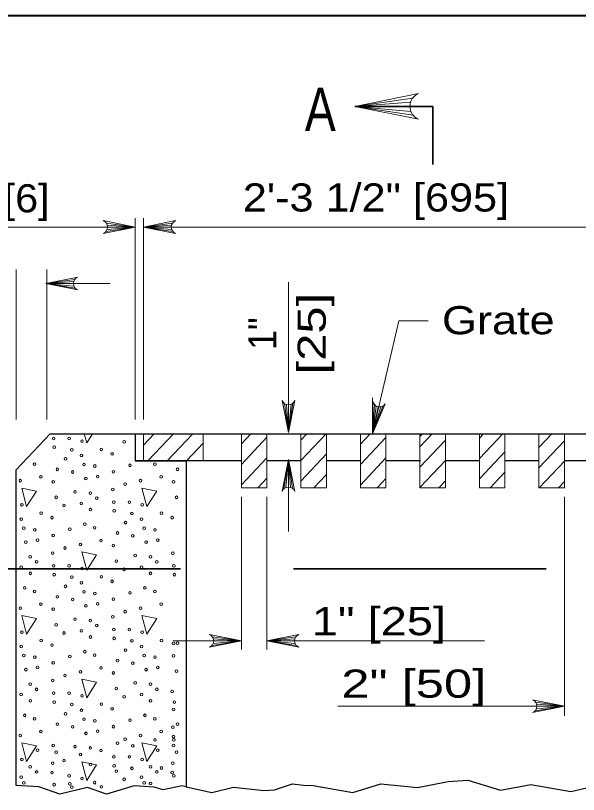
# Model space of a CAD drawing. Extents: x -410.5 to -376.5, y 1617.6 to 1661.6.
# Drawn here: x -394.78 to -391.656, y 1634.741 to 1639.062 of the extents above; entities that cross this region are included whole.
import ezdxf
from ezdxf.enums import TextEntityAlignment as Align

# ---------------------------------------------------------------- set-up
doc = ezdxf.new("R2010")
doc.units = 0
doc.header["$LTSCALE"] = 0.062
doc.layers.add('1', color=7, linetype='Continuous', lineweight=13)

msp = doc.modelspace()

# ---------------------------------------------------------------- linework, layer by layer
at = {"layer": '1', "lineweight": 25}
for p, q in [((-408.45475, 1639.06183), (-376.95475, 1639.06183)), ((-394.1165, 1636.74175), (-390.8125, 1636.74175)), ((-393.52675, 1636.59183), (-394.1165, 1636.59183)), ((-393.83325, 1636.59183), (-393.83325, 1634.78325)), ((-393.19667, 1636.59183), (-393.38483, 1636.59183)), ((-392.86658, 1636.59183), (-393.0545, 1636.59183)), ((-392.532, 1636.59183), (-392.72408, 1636.59183)), ((-392.20633, 1636.59183), (-392.39367, 1636.59183)), ((-391.87483, 1636.59183), (-392.06325, 1636.59183)), ((-391.54408, 1636.59183), (-391.73283, 1636.59183))]:
    msp.add_line(p, q, dxfattribs=at)
at = {"layer": '1'}
for p, q in [((-392.57667, 1638.603), (-392.89717, 1638.55817)), ((-392.5875, 1638.58083), (-392.89717, 1638.55817)), ((-392.59083, 1638.55817), (-392.89717, 1638.55817)), ((-392.58517, 1638.52933), (-392.89717, 1638.55817)), ((-392.57283, 1638.50858), (-392.89717, 1638.55817)), ((-394.1165, 1636.82042), (-394.1165, 1637.93875)), ((-394.06925, 1636.82042), (-394.06925, 1637.93875)), ((-395.37925, 1637.88875), (-394.1165, 1637.88875)), ((-394.27858, 1637.864), (-394.1165, 1637.88875)), ((-394.27675, 1637.91117), (-394.1165, 1637.88875)), ((-394.2725, 1637.87442), (-394.1165, 1637.88875)), ((-394.27125, 1637.90008), (-394.1165, 1637.88875)), ((-394.26967, 1637.88875), (-394.1165, 1637.88875)), ((-393.909, 1637.91117), (-394.06925, 1637.88875)), ((-393.91442, 1637.90008), (-394.06925, 1637.88875)), ((-393.91608, 1637.88875), (-394.06925, 1637.88875)), ((-393.91325, 1637.87442), (-394.06925, 1637.88875)), ((-393.90717, 1637.864), (-394.06925, 1637.88875)), ((-391.80342, 1637.88875), (-390.85967, 1637.88875)), ((-394.77725, 1636.82042), (-394.77725, 1637.65358)), ((-394.60625, 1636.82042), (-394.60625, 1637.65358)), ((-394.45183, 1637.59733), (-394.61208, 1637.57492)), ((-394.45725, 1637.58625), (-394.61208, 1637.57492)), ((-394.61208, 1637.57492), (-394.25475, 1637.57492)), ((-394.45892, 1637.57492), (-394.61208, 1637.57492)), ((-394.45608, 1637.56058), (-394.61208, 1637.57492)), ((-394.44992, 1637.55017), (-394.61208, 1637.57492)), ((-393.26533, 1637.58325), (-393.26533, 1636.74933)), ((-393.26533, 1636.74933), (-393.26533, 1636.94917)), ((-392.7995, 1636.74175), (-392.7995, 1636.94158)), ((-393.28775, 1636.90958), (-393.26533, 1636.74933)), ((-393.27667, 1636.90408), (-393.26533, 1636.74933)), ((-393.24058, 1636.91142), (-393.26533, 1636.74933)), ((-393.25092, 1636.90533), (-393.26533, 1636.74933)), ((-393.26533, 1636.9025), (-393.26533, 1636.74933)), ((-392.78758, 1636.90308), (-392.7995, 1636.74175)), ((-392.77792, 1636.89542), (-392.7995, 1636.74175)), ((-392.74108, 1636.89492), (-392.7995, 1636.74175)), ((-392.76717, 1636.8915), (-392.7995, 1636.74175)), ((-392.75242, 1636.89117), (-392.7995, 1636.74175)), ((-394.1165, 1636.74175), (-394.1165, 1636.59183)), ((-394.06925, 1636.74175), (-394.06925, 1636.59183)), ((-394.06925, 1636.67933), (-394.01042, 1636.74167)), ((-394.06925, 1636.73592), (-394.06383, 1636.74167)), ((-394.04508, 1636.59192), (-393.90358, 1636.74167)), ((-393.93833, 1636.59192), (-393.79683, 1636.74167)), ((-393.73883, 1636.59183), (-393.73883, 1636.74175)), ((-393.5265, 1636.68542), (-393.47325, 1636.74175)), ((-393.5265, 1636.57233), (-393.38483, 1636.72225)), ((-393.19608, 1636.59308), (-393.05567, 1636.74175)), ((-393.19608, 1636.70608), (-393.1625, 1636.74175)), ((-392.86567, 1636.68375), (-392.81092, 1636.74175)), ((-392.86567, 1636.74033), (-392.86433, 1636.74175)), ((-392.86567, 1636.57067), (-392.72408, 1636.72058)), ((-392.53533, 1636.67), (-392.46758, 1636.74175)), ((-392.53525, 1636.72667), (-392.521, 1636.74175)), ((-392.53525, 1636.557), (-392.39367, 1636.70692)), ((-392.20483, 1636.60475), (-392.07542, 1636.74175)), ((-392.20483, 1636.71783), (-392.18225, 1636.74175)), ((-391.8745, 1636.66617), (-391.80317, 1636.74175)), ((-393.8315, 1636.59192), (-393.73883, 1636.69)), ((-391.8745, 1636.55308), (-391.73283, 1636.70308)), ((-393.19608, 1636.47992), (-393.0545, 1636.62983)), ((-392.20483, 1636.49158), (-392.06325, 1636.64158)), ((-393.5265, 1636.45925), (-393.38483, 1636.60925)), ((-393.29008, 1636.43725), (-393.26533, 1636.59942)), ((-393.27975, 1636.44342), (-393.26533, 1636.59942)), ((-393.26533, 1636.44625), (-393.26533, 1636.59942)), ((-393.254, 1636.44458), (-393.26533, 1636.59942)), ((-393.24292, 1636.43917), (-393.26533, 1636.59942)), ((-393.26533, 1636.59942), (-393.26533, 1636.19908)), ((-392.86567, 1636.45767), (-392.72408, 1636.60758)), ((-392.53525, 1636.44392), (-392.39367, 1636.59392)), ((-391.87275, 1636.44192), (-391.73283, 1636.59)), ((-393.436, 1636.44192), (-393.38483, 1636.49608)), ((-393.12517, 1636.44192), (-393.0545, 1636.51683)), ((-392.77367, 1636.44192), (-392.72408, 1636.49442)), ((-392.145, 1636.44192), (-392.06325, 1636.5285)), ((-392.43042, 1636.44192), (-392.39367, 1636.48075)), ((-391.76592, 1636.44192), (-391.73283, 1636.47683)), ((-394.74583, 1636.44017), (-394.71883, 1636.33775)), ((-393.5265, 1636.39192), (-393.5265, 1635.54608)), ((-393.38483, 1636.39192), (-393.38483, 1635.54608)), ((-391.73283, 1636.39192), (-391.73283, 1635.17808)), ((-394.74583, 1635.7335), (-394.71883, 1635.631)), ((-393.90783, 1635.59275), (-393.5265, 1635.59275)), ((-393.68858, 1635.568), (-393.5265, 1635.59275)), ((-393.68667, 1635.61517), (-393.5265, 1635.59275)), ((-393.6825, 1635.57842), (-393.5265, 1635.59275)), ((-393.68125, 1635.60408), (-393.5265, 1635.59275)), ((-393.67967, 1635.59275), (-393.5265, 1635.59275)), ((-393.22458, 1635.61517), (-393.38483, 1635.59275)), ((-393.23008, 1635.60408), (-393.38483, 1635.59275)), ((-393.38483, 1635.59275), (-392.17617, 1635.59275)), ((-393.23167, 1635.59275), (-393.38483, 1635.59275)), ((-393.22883, 1635.57842), (-393.38483, 1635.59275)), ((-393.22275, 1635.568), (-393.38483, 1635.59275)), ((-391.89308, 1635.25267), (-391.73283, 1635.23025)), ((-391.88767, 1635.24158), (-391.73283, 1635.23025)), ((-392.99025, 1635.23025), (-391.73283, 1635.23025)), ((-391.895, 1635.2055), (-391.73283, 1635.23025)), ((-391.88883, 1635.21583), (-391.73283, 1635.23025)), ((-391.886, 1635.23025), (-391.73283, 1635.23025)), ((-394.66392, 1635.01083), (-394.74583, 1635.02675))]:
    msp.add_line(p, q, dxfattribs=at)
at = {"layer": '1', "lineweight": 35}
for p, q in [((-392.4645, 1638.55817), (-392.89717, 1638.55817)), ((-392.4645, 1638.23483), (-392.4645, 1638.55817)), ((-395.311, 1635.99217), (-393.8645, 1635.99217)), ((-393.23742, 1635.99217), (-392.71767, 1635.99217)), ((-392.71767, 1635.99217), (-391.83425, 1635.99217))]:
    msp.add_line(p, q, dxfattribs=at)
at = {"layer": '1', "lineweight": 40}
msp.add_lwpolyline([(-408.45475, 1639.06183), (-376.95475, 1639.06183), (-376.95475, 1618.06183), (-408.45475, 1618.06183)], close=True, dxfattribs=at)
msp.add_lwpolyline([(-408.45475, 1639.06183), (-376.95475, 1639.06183), (-376.95475, 1618.06183), (-408.45475, 1618.06183)], close=True, dxfattribs=at)
at = {"layer": '1'}
for points in [[(-392.54317, 1638.48733), (-392.89717, 1638.55817), (-392.54317, 1638.62892)], [(-394.2935, 1637.85342), (-394.1165, 1637.88875), (-394.2935, 1637.92417)], [(-393.89225, 1637.85342), (-394.06925, 1637.88875), (-393.89225, 1637.92417)], [(-394.06925, 1637.88875), (-392.576, 1637.88875), (-391.80342, 1637.88875)], [(-394.43508, 1637.53958), (-394.61208, 1637.57492), (-394.43508, 1637.61033)], [(-392.7995, 1636.74175), (-392.65317, 1637.36825), (-392.49008, 1637.36825)], [(-393.22992, 1636.92633), (-393.26533, 1636.74933), (-393.30075, 1636.92633)], [(-392.7275, 1636.90725), (-392.7995, 1636.74175), (-392.79675, 1636.92225)], [(-394.39842, 1636.74167), (-394.38508, 1636.69108), (-394.35292, 1636.74167)], [(-393.30075, 1636.42242), (-393.26533, 1636.59942), (-393.22992, 1636.42242)], [(-394.71883, 1636.33775), (-394.66392, 1636.42425), (-394.74583, 1636.44017)], [(-394.71883, 1635.631), (-394.66392, 1635.7175), (-394.74583, 1635.7335)], [(-393.7035, 1635.55742), (-393.5265, 1635.59275), (-393.7035, 1635.62817)], [(-393.20783, 1635.55742), (-393.38483, 1635.59275), (-393.20783, 1635.62817)], [(-391.90983, 1635.19483), (-391.73283, 1635.23025), (-391.90983, 1635.26567)], [(-394.74583, 1635.02675), (-394.71883, 1634.92433), (-394.66392, 1635.01083)]]:
    msp.add_lwpolyline(points, dxfattribs=at)
at = {"layer": '1', "lineweight": 25}
for points in [[(-393.83325, 1634.78325), (-393.85467, 1634.78808), (-393.96075, 1634.76608), (-394.011, 1634.78242), (-394.12183, 1634.78875), (-394.27542, 1634.74258), (-394.38142, 1634.78033), (-394.53508, 1634.74325), (-394.6515, 1634.78308), (-394.77725, 1634.79117), (-394.77725, 1636.54183), (-394.5885, 1636.74175), (-394.1165, 1636.74175)], [(-394.1165, 1636.74175), (-394.1165, 1636.59183), (-393.83325, 1636.59183)], [(-393.83325, 1634.78325), (-393.68983, 1634.75117), (-393.57033, 1634.78225), (-393.40175, 1634.76358), (-393.34308, 1634.76642), (-393.2425, 1634.80067), (-393.18192, 1634.79342), (-393.12783, 1634.79125), (-392.90825, 1634.75217), (-392.75167, 1634.80033), (-392.54808, 1634.77958), (-392.37933, 1634.81358), (-392.26933, 1634.82042), (-392.08858, 1634.76517), (-391.91983, 1634.79617), (-391.69733, 1634.75808), (-391.53892, 1634.79417), (-391.48967, 1634.80517), (-391.23017, 1634.767), (-391.09567, 1634.79958)]]:
    msp.add_lwpolyline(points, dxfattribs=at)
at = {"layer": '1'}
for points in [[(-393.5265, 1636.74175), (-393.5265, 1636.44192), (-393.38483, 1636.44192), (-393.38483, 1636.74175)], [(-393.19608, 1636.74175), (-393.19608, 1636.44192), (-393.0545, 1636.44192), (-393.0545, 1636.74175)], [(-392.86567, 1636.74175), (-392.86567, 1636.44192), (-392.72408, 1636.44192), (-392.72408, 1636.74175)], [(-392.53525, 1636.74175), (-392.53525, 1636.44192), (-392.39367, 1636.44192), (-392.39367, 1636.74175)], [(-392.20483, 1636.74175), (-392.20483, 1636.44192), (-392.06325, 1636.44192), (-392.06325, 1636.74175)], [(-391.8745, 1636.74175), (-391.8745, 1636.44192), (-391.73283, 1636.44192), (-391.73283, 1636.74175)], [(-394.07833, 1636.44017), (-394.05133, 1636.33775), (-393.99633, 1636.42425)], [(-394.41208, 1636.08683), (-394.38508, 1635.98442), (-394.33008, 1636.07083)], [(-394.07833, 1635.7335), (-394.05133, 1635.631), (-393.99633, 1635.7175)], [(-394.41208, 1635.38008), (-394.38508, 1635.27775), (-394.33008, 1635.36417)], [(-394.07833, 1635.02675), (-394.05133, 1634.92433), (-393.99633, 1635.01083)], [(-394.41208, 1634.92158), (-394.38508, 1634.81917), (-394.33008, 1634.90558)]]:
    msp.add_lwpolyline(points, close=True, dxfattribs=at)
for centre, radius, start, end in [((-392.51454, 1638.55823), 0.0764, 112.08782, 247.91395), ((-394.30776, 1637.88882), 0.0382, 292.08605, 67.91218), ((-393.87797, 1637.88882), 0.0382, 112.08782, 247.91395), ((-394.42078, 1637.57499), 0.0382, 112.08782, 247.91395), ((-393.26537, 1636.9406), 0.0382, 202.08782, 337.91395), ((-392.75912, 1636.9287), 0.0382, 189.88947, 325.7156), ((-393.26529, 1636.40809), 0.0382, 22.08782, 157.91395), ((-393.71776, 1635.59282), 0.0382, 292.08605, 67.91218), ((-393.19357, 1635.59282), 0.0382, 112.08782, 247.91395), ((-391.92416, 1635.23029), 0.0382, 292.08605, 67.91218)]:
    msp.add_arc(centre, radius, start, end, dxfattribs=at)
for centre, major_axis in [((-394.56882, 1636.71583), (0, -0.00756)), ((-394.48227, 1636.71583), (0, 0.00756)), ((-394.41112, 1636.70152), (0, -0.00756)), ((-394.56615, 1636.66719), (0, -0.00756)), ((-394.30387, 1636.65476), (0, -0.00756)), ((-394.17766, 1636.69675), (0, 0.00756)), ((-394.46786, 1636.65288), (0, 0.00756)), ((-394.41474, 1636.62137), (0, 0.00756)), ((-394.24441, 1636.62997), (0, -0.00756)), ((-394.67456, 1636.57337), (0, -0.00756)), ((-394.50307, 1636.60229), (0, 0.00756)), ((-394.40027, 1636.57178), (0, 0.00756)), ((-394.00706, 1636.57337), (0, -0.00756)), ((-394.5484, 1636.54475), (0, 0.00756)), ((-394.46341, 1636.52979), (0, 0.00756)), ((-394.33992, 1636.56313), (0, -0.00756)), ((-394.23718, 1636.53068), (0, -0.00756)), ((-394.14495, 1636.56672), (0, -0.00756)), ((-393.8809, 1636.54475), (0, 0.00756)), ((-394.75389, 1636.48174), (0, -0.00756)), ((-394.63946, 1636.5037), (0, 0.00756)), ((-394.38954, 1636.49352), (0, 0.00756)), ((-394.32462, 1636.505), (0, -0.00756)), ((-394.08638, 1636.48174), (0, -0.00756)), ((-393.97196, 1636.5037), (0, 0.00756)), ((-394.57093, 1636.47508), (0, 0.00756)), ((-394.17204, 1636.46171), (0, -0.00756)), ((-393.90342, 1636.47508), (0, 0.00756)), ((-394.45017, 1636.41978), (0, 0.00756)), ((-394.36512, 1636.41242), (0, 0.00756)), ((-394.24046, 1636.43309), (0, -0.00756)), ((-394.55469, 1636.38922), (0, 0.00756)), ((-394.41501, 1636.35583), (0, 0.00756)), ((-394.32968, 1636.38445), (0, -0.00756)), ((-394.23507, 1636.36248), (0, -0.00756)), ((-394.14851, 1636.36248), (0, 0.00756)), ((-393.88718, 1636.38922), (0, 0.00756)), ((-394.74487, 1636.34817), (0, -0.00756)), ((-394.51141, 1636.3434), (0, 0.00756)), ((-394.36423, 1636.32114), (0, -0.00756)), ((-394.23239, 1636.31384), (0, -0.00756)), ((-394.07737, 1636.34817), (0, -0.00756)), ((-394.74849, 1636.26802), (0, 0.00756)), ((-394.63763, 1636.30141), (0, -0.00756)), ((-394.57816, 1636.27662), (0, -0.00756)), ((-394.1341, 1636.29953), (0, 0.00756)), ((-394.08098, 1636.26802), (0, 0.00756)), ((-393.97012, 1636.30141), (0, -0.00756)), ((-393.91066, 1636.27662), (0, -0.00756)), ((-394.39577, 1636.24005), (0, -0.00756)), ((-394.16932, 1636.24894), (0, 0.00756)), ((-394.73403, 1636.21843), (0, 0.00756)), ((-394.67367, 1636.20978), (0, -0.00756)), ((-394.47871, 1636.21337), (0, -0.00756)), ((-394.34081, 1636.22002), (0, -0.00756)), ((-394.21465, 1636.1914), (0, 0.00756)), ((-394.06652, 1636.21843), (0, 0.00756)), ((-394.00617, 1636.20978), (0, -0.00756)), ((-394.72329, 1636.14017), (0, 0.00756)), ((-394.65838, 1636.15165), (0, -0.00756)), ((-394.57093, 1636.17733), (0, -0.00756)), ((-394.30571, 1636.15035), (0, 0.00756)), ((-394.12965, 1636.17644), (0, 0.00756)), ((-394.05578, 1636.14017), (0, 0.00756)), ((-393.99087, 1636.15165), (0, -0.00756)), ((-394.5058, 1636.10836), (0, -0.00756)), ((-394.42013, 1636.12839), (0, -0.00756)), ((-394.23718, 1636.12173), (0, 0.00756)), ((-394.69887, 1636.05907), (0, 0.00756)), ((-394.57421, 1636.07974), (0, -0.00756)), ((-394.11642, 1636.06643), (0, 0.00756)), ((-394.03136, 1636.05907), (0, 0.00756)), ((-393.90671, 1636.07974), (0, -0.00756)), ((-394.66344, 1636.0311), (0, -0.00756)), ((-394.56882, 1636.00913), (0, -0.00756)), ((-394.48227, 1636.00913), (0, 0.00756)), ((-394.22094, 1636.03587), (0, 0.00756)), ((-393.99593, 1636.0311), (0, -0.00756)), ((-393.90131, 1636.00913), (0, -0.00756)), ((-394.74877, 1636.00248), (0, 0.00756)), ((-394.69798, 1635.96779), (0, -0.00756)), ((-394.41112, 1635.99482), (0, -0.00756)), ((-394.17766, 1635.99005), (0, 0.00756)), ((-394.08126, 1636.00248), (0, 0.00756)), ((-394.03047, 1635.96779), (0, -0.00756)), ((-394.56615, 1635.96049), (0, -0.00756)), ((-394.46786, 1635.94618), (0, 0.00756)), ((-394.30387, 1635.94806), (0, -0.00756)), ((-394.24441, 1635.92327), (0, -0.00756)), ((-393.89864, 1635.96049), (0, -0.00756)), ((-394.72952, 1635.8867), (0, -0.00756)), ((-394.50307, 1635.89559), (0, 0.00756)), ((-394.41474, 1635.91467), (0, 0.00756)), ((-394.06201, 1635.8867), (0, -0.00756)), ((-394.67456, 1635.86667), (0, -0.00756)), ((-394.5484, 1635.83805), (0, 0.00756)), ((-394.40027, 1635.86508), (0, 0.00756)), ((-394.33992, 1635.85643), (0, -0.00756)), ((-394.14495, 1635.86002), (0, -0.00756)), ((-394.00706, 1635.86667), (0, -0.00756)), ((-394.63946, 1635.797), (0, 0.00756)), ((-394.46341, 1635.82309), (0, 0.00756)), ((-394.32462, 1635.7983), (0, -0.00756)), ((-394.23718, 1635.82398), (0, -0.00756)), ((-393.97196, 1635.797), (0, 0.00756)), ((-394.75389, 1635.77504), (0, -0.00756)), ((-394.57093, 1635.76838), (0, 0.00756)), ((-394.38954, 1635.78682), (0, 0.00756)), ((-394.17204, 1635.75501), (0, -0.00756)), ((-394.08638, 1635.77504), (0, -0.00756)), ((-394.45017, 1635.71308), (0, 0.00756)), ((-394.36512, 1635.70572), (0, 0.00756)), ((-394.24046, 1635.72639), (0, -0.00756)), ((-394.55469, 1635.68252), (0, 0.00756)), ((-394.32968, 1635.67775), (0, -0.00756)), ((-394.74487, 1635.64147), (0, -0.00756)), ((-394.51141, 1635.6367), (0, 0.00756)), ((-394.41501, 1635.64913), (0, 0.00756)), ((-394.23507, 1635.65578), (0, -0.00756)), ((-394.14851, 1635.65578), (0, 0.00756)), ((-394.07737, 1635.64147), (0, -0.00756)), ((-394.63763, 1635.59471), (0, -0.00756)), ((-394.36423, 1635.61444), (0, -0.00756)), ((-394.23239, 1635.60714), (0, -0.00756)), ((-394.1341, 1635.59283), (0, 0.00756)), ((-393.97012, 1635.59471), (0, -0.00756)), ((-393.90342, 1635.57807), (0, -0.00756)), ((-393.8809, 1635.57989), (0, 0.00756)), ((-394.74849, 1635.56132), (0, 0.00756)), ((-394.57816, 1635.56992), (0, -0.00756)), ((-394.39577, 1635.53335), (0, -0.00756)), ((-394.16932, 1635.54224), (0, 0.00756)), ((-394.08098, 1635.56132), (0, 0.00756)), ((-394.73403, 1635.51173), (0, 0.00756)), ((-394.67367, 1635.50308), (0, -0.00756)), ((-394.47871, 1635.50667), (0, -0.00756)), ((-394.34081, 1635.51332), (0, -0.00756)), ((-394.06652, 1635.51173), (0, 0.00756)), ((-394.00617, 1635.50308), (0, -0.00756)), ((-393.90342, 1635.51022), (0, 0.00756)), ((-394.65838, 1635.44495), (0, -0.00756)), ((-394.57093, 1635.47063), (0, -0.00756)), ((-394.21465, 1635.4847), (0, 0.00756)), ((-394.12965, 1635.46974), (0, 0.00756)), ((-393.99087, 1635.44495), (0, -0.00756)), ((-394.72329, 1635.43347), (0, 0.00756)), ((-394.5058, 1635.40166), (0, -0.00756)), ((-394.42013, 1635.42169), (0, -0.00756)), ((-394.30571, 1635.44365), (0, 0.00756)), ((-394.23718, 1635.41503), (0, 0.00756)), ((-394.05578, 1635.43347), (0, 0.00756)), ((-393.88718, 1635.42435), (0, 0.00756)), ((-394.57421, 1635.37304), (0, -0.00756)), ((-394.11642, 1635.35973), (0, 0.00756)), ((-394.69887, 1635.35237), (0, 0.00756)), ((-394.66344, 1635.3244), (0, -0.00756)), ((-394.22094, 1635.32917), (0, 0.00756)), ((-394.03136, 1635.35237), (0, 0.00756)), ((-393.99593, 1635.3244), (0, -0.00756)), ((-394.74877, 1635.29578), (0, 0.00756)), ((-394.56882, 1635.30243), (0, -0.00756)), ((-394.48227, 1635.30243), (0, 0.00756)), ((-394.41112, 1635.28812), (0, -0.00756)), ((-394.17766, 1635.28335), (0, 0.00756)), ((-394.08126, 1635.29578), (0, 0.00756)), ((-393.91066, 1635.31175), (0, -0.00756)), ((-394.69798, 1635.26109), (0, -0.00756)), ((-394.56615, 1635.25379), (0, -0.00756)), ((-394.46786, 1635.23948), (0, 0.00756)), ((-394.30387, 1635.24136), (0, -0.00756)), ((-394.03047, 1635.26109), (0, -0.00756)), ((-393.89864, 1635.25379), (0, -0.00756)), ((-394.50307, 1635.18889), (0, 0.00756)), ((-394.41474, 1635.20797), (0, 0.00756)), ((-394.24441, 1635.21657), (0, -0.00756)), ((-393.90342, 1635.21246), (0, -0.00756)), ((-394.72952, 1635.18), (0, -0.00756)), ((-394.67456, 1635.15997), (0, -0.00756)), ((-394.40027, 1635.15838), (0, 0.00756)), ((-394.33992, 1635.14973), (0, -0.00756)), ((-394.14495, 1635.15332), (0, -0.00756)), ((-394.06201, 1635.18), (0, -0.00756)), ((-394.00706, 1635.15997), (0, -0.00756)), ((-394.5484, 1635.13135), (0, 0.00756)), ((-394.46341, 1635.11639), (0, 0.00756)), ((-394.23718, 1635.11728), (0, -0.00756)), ((-393.90671, 1635.11488), (0, -0.00756)), ((-393.8809, 1635.13135), (0, 0.00756)), ((-394.75389, 1635.06834), (0, -0.00756)), ((-394.63946, 1635.0903), (0, 0.00756)), ((-394.38954, 1635.08012), (0, 0.00756)), ((-394.32462, 1635.0916), (0, -0.00756)), ((-394.08638, 1635.06834), (0, -0.00756)), ((-393.97196, 1635.0903), (0, 0.00756)), ((-393.90342, 1635.06168), (0, 0.00756)), ((-394.21465, 1635.02619), (0, 0.00756)), ((-394.17204, 1635.04831), (0, -0.00756)), ((-394.00617, 1635.04456), (0, -0.00756)), ((-393.90131, 1635.04427), (0, -0.00756)), ((-394.65838, 1634.98644), (0, -0.00756)), ((-394.57093, 1635.01211), (0, -0.00756)), ((-394.55469, 1634.97582), (0, 0.00756)), ((-394.45017, 1635.00638), (0, 0.00756)), ((-394.36512, 1634.99902), (0, 0.00756)), ((-394.30571, 1634.98514), (0, 0.00756)), ((-394.12965, 1635.01123), (0, 0.00756)), ((-393.99087, 1634.98644), (0, -0.00756)), ((-393.90343, 1635.01211), (0, -0.00756)), ((-393.88718, 1634.97582), (0, 0.00756)), ((-394.74487, 1634.93477), (0, -0.00756)), ((-394.51141, 1634.93), (0, 0.00756)), ((-394.42013, 1634.96317), (0, -0.00756)), ((-394.23507, 1634.94908), (0, -0.00756)), ((-394.14851, 1634.94908), (0, 0.00756)), ((-394.07737, 1634.93477), (0, -0.00756)), ((-394.69887, 1634.89386), (0, 0.00756)), ((-394.57422, 1634.91453), (0, -0.00756)), ((-394.36423, 1634.90774), (0, -0.00756)), ((-394.23239, 1634.90044), (0, -0.00756)), ((-394.1341, 1634.88613), (0, 0.00756)), ((-394.03136, 1634.89386), (0, 0.00756)), ((-393.97012, 1634.88801), (0, -0.00756)), ((-393.90671, 1634.91453), (0, -0.00756)), ((-394.66344, 1634.86588), (0, -0.00756)), ((-394.57816, 1634.86322), (0, -0.00756)), ((-394.48227, 1634.84392), (0, 0.00756)), ((-394.22094, 1634.87065), (0, 0.00756)), ((-393.99593, 1634.86588), (0, -0.00756)), ((-393.91066, 1634.86322), (0, -0.00756)), ((-393.90131, 1634.84392), (0, -0.00756)), ((-394.74877, 1634.83726), (0, 0.00756)), ((-394.73403, 1634.80503), (0, 0.00756)), ((-394.47871, 1634.79997), (0, -0.00756)), ((-394.41112, 1634.82961), (0, -0.00756)), ((-394.34081, 1634.80662), (0, -0.00756)), ((-394.17766, 1634.82484), (0, 0.00756)), ((-394.08126, 1634.83726), (0, 0.00756)), ((-394.06652, 1634.80503), (0, 0.00756)), ((-394.03047, 1634.80258), (0, -0.00756)), ((-394.56615, 1634.79527), (0, -0.00756)), ((-394.46786, 1634.78096), (0, 0.00756)), ((-394.30387, 1634.78285), (0, -0.00756))]:
    msp.add_ellipse(centre, major_axis=major_axis, ratio=0.944543, dxfattribs=at)

# ---------------------------------------------------------------- texts
at = {"layer": '1', "width": 0.8}
msp.add_text('A', height=0.24, dxfattribs=at).set_placement((-393.08842, 1638.422), align=Align.CENTER)
at = {"layer": '1'}
for s, width, p in [('1/4" [6]', 1.1, (-395.3105, 1637.97025)), ('2\'-3 1/2" [695]', 1.15, (-393.51858, 1637.97483)), ('Grate', 1.2, (-392.41358, 1637.29392)), ('1" [25]', 1.25, (-393.13575, 1635.62442)), ('2" [50]', 1.35, (-392.97175, 1635.278))]:
    msp.add_text(s, height=0.156, dxfattribs=dict(at, width=width)).set_placement(p)
for s, width, p in [('[25]', 1.3, (-393.05825, 1637.29746)), ('1"', 0.95, (-393.33225, 1637.29746))]:
    msp.add_text(s, height=0.156, rotation=90, dxfattribs=dict(at, width=width)).set_placement(p, align=Align.CENTER)

doc.saveas('drawing.dxf')
